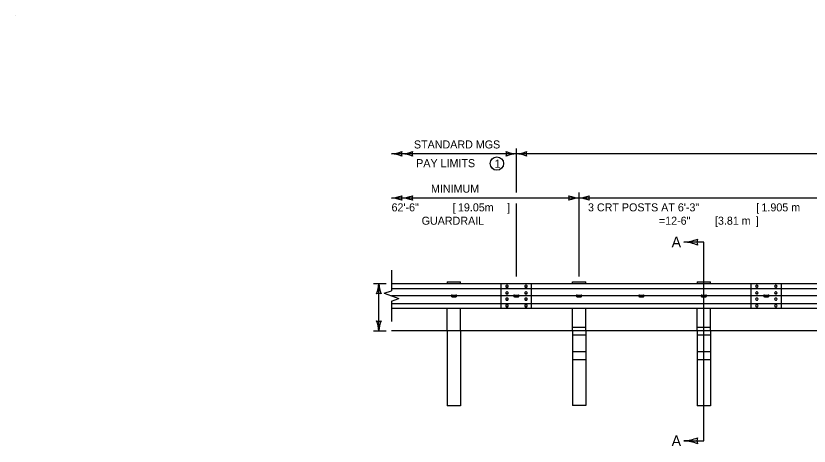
# Model space of a CAD drawing. Extents: x 49991.4 to 50044.5, y 49987.6 to 50011.4.
# Drawn here: x 50021.04 to 50026.98, y 50005.3 to 50008.52 of the extents above; entities that cross this region are included whole.
import ezdxf

# ---------------------------------------------------------------- set-up
doc = ezdxf.new("R2010")
doc.units = 0
for name, color, linetype in [('Level 1', 7, 'Continuous'), ('Level 2', 7, 'Continuous'), ('Level 3', 7, 'Continuous'), ('Level 4', 7, 'Continuous'), ('Level 5', 7, 'Continuous'), ('Level 6', 7, 'Continuous')]:
    doc.layers.add(name, color=color, linetype=linetype)

msp = doc.modelspace()

# ---------------------------------------------------------------- linework, layer by layer
at = {"layer": 'Level 1'}
for p, q in [((50021.0378, 50008.5236), (50021.0378, 50008.5236)), ((50024.2697, 50006.5335), (50024.2697, 50006.5203)), ((50024.2697, 50006.5335), (50024.3697, 50006.5335)), ((50024.3697, 50006.5203), (50024.3697, 50006.5335)), ((50025.2078, 50006.5203), (50025.2078, 50006.5335)), ((50025.2078, 50006.5335), (50025.3077, 50006.5335)), ((50025.3077, 50006.5203), (50025.3077, 50006.5335)), ((50026.1422, 50006.5335), (50026.1422, 50006.5203)), ((50026.1422, 50006.5335), (50026.2422, 50006.5335)), ((50026.2422, 50006.5203), (50026.2422, 50006.5335)), ((50023.8525, 50006.5203), (50035.1185, 50006.5203)), ((50023.8525, 50006.4843), (50035.1185, 50006.4843)), ((50024.6747, 50006.335), (50024.6747, 50006.5196)), ((50024.7189, 50006.508), (50024.7153, 50006.508)), ((50024.7189, 50006.4929), (50024.7153, 50006.4929)), ((50024.8612, 50006.508), (50024.8576, 50006.508)), ((50024.8612, 50006.4929), (50024.8576, 50006.4929)), ((50026.5472, 50006.335), (50026.5472, 50006.5196)), ((50026.5914, 50006.508), (50026.5878, 50006.508)), ((50026.5914, 50006.4929), (50026.5878, 50006.4929)), ((50026.7336, 50006.508), (50026.73, 50006.508)), ((50026.7336, 50006.4929), (50026.73, 50006.4929)), ((50024.3062, 50006.4342), (50024.3353, 50006.4342)), ((50024.3062, 50006.4217), (50024.3353, 50006.4217)), ((50024.7189, 50006.4581), (50024.7153, 50006.4581)), ((50024.7189, 50006.443), (50024.7153, 50006.443)), ((50024.7189, 50006.4116), (50024.7153, 50006.4116)), ((50024.7734, 50006.4342), (50024.8026, 50006.4342)), ((50024.7734, 50006.4217), (50024.8026, 50006.4217)), ((50024.8612, 50006.4581), (50024.8576, 50006.4581)), ((50024.8612, 50006.443), (50024.8576, 50006.443)), ((50024.8612, 50006.4116), (50024.8576, 50006.4116)), ((50025.2432, 50006.4342), (50025.2723, 50006.4342)), ((50025.2432, 50006.4217), (50025.2723, 50006.4217)), ((50025.7104, 50006.4342), (50025.7396, 50006.4342)), ((50025.7104, 50006.4217), (50025.7396, 50006.4217)), ((50026.1776, 50006.4342), (50026.2068, 50006.4342)), ((50026.1776, 50006.4217), (50026.2068, 50006.4217)), ((50026.5914, 50006.4581), (50026.5878, 50006.4581)), ((50026.5914, 50006.443), (50026.5878, 50006.443)), ((50026.5914, 50006.4116), (50026.5878, 50006.4116)), ((50026.6459, 50006.4342), (50026.675, 50006.4342)), ((50026.6459, 50006.4217), (50026.675, 50006.4217)), ((50026.7336, 50006.4581), (50026.73, 50006.4581)), ((50026.7336, 50006.443), (50026.73, 50006.443)), ((50026.7336, 50006.4116), (50026.73, 50006.4116)), ((50023.8525, 50006.3717), (50035.1185, 50006.3717)), ((50024.7189, 50006.3965), (50024.7153, 50006.3965)), ((50024.7189, 50006.3617), (50024.7153, 50006.3617)), ((50024.7189, 50006.3466), (50024.7153, 50006.3466)), ((50024.8612, 50006.3965), (50024.8576, 50006.3965)), ((50024.8612, 50006.3617), (50024.8576, 50006.3617)), ((50024.8612, 50006.3466), (50024.8576, 50006.3466)), ((50026.5914, 50006.3965), (50026.5878, 50006.3965)), ((50026.5914, 50006.3617), (50026.5878, 50006.3617)), ((50026.5914, 50006.3466), (50026.5878, 50006.3466)), ((50026.7336, 50006.3965), (50026.73, 50006.3965)), ((50026.7336, 50006.3617), (50026.73, 50006.3617)), ((50026.7336, 50006.3466), (50026.73, 50006.3466)), ((50023.8525, 50006.3357), (50035.1185, 50006.3357)), ((50024.2697, 50006.1659), (50024.2697, 50006.3357)), ((50024.3697, 50006.1659), (50024.3697, 50006.3357)), ((50025.2077, 50006.1659), (50025.2077, 50006.3357)), ((50025.3077, 50006.1659), (50025.3077, 50006.3357)), ((50026.1422, 50006.1659), (50026.1422, 50006.3357)), ((50026.2421, 50006.1659), (50026.2421, 50006.3357)), ((50035.1185, 50006.1659), (50023.8525, 50006.1659))]:
    msp.add_line(p, q, dxfattribs=at)
for centre, start, end in [((50024.3062, 50006.428), 90, 180), ((50024.3062, 50006.428), 180, 270), ((50024.3353, 50006.428), 360, 90), ((50024.3353, 50006.428), 270, 0), ((50024.7734, 50006.428), 90, 180), ((50024.7734, 50006.428), 180, 270), ((50024.8026, 50006.428), 360, 90), ((50024.8026, 50006.428), 270, 0), ((50025.2432, 50006.428), 90, 180), ((50025.2432, 50006.428), 180, 270), ((50025.2723, 50006.428), 360, 90), ((50025.2723, 50006.428), 270, 0), ((50025.7104, 50006.428), 90, 180), ((50025.7104, 50006.428), 180, 270), ((50025.7396, 50006.428), 360, 90), ((50025.7396, 50006.428), 270, 0), ((50026.1776, 50006.428), 90, 180), ((50026.1776, 50006.428), 180, 270), ((50026.2068, 50006.428), 360, 90), ((50026.2068, 50006.428), 270, 0), ((50026.6459, 50006.428), 90, 180), ((50026.6459, 50006.428), 180, 270), ((50026.675, 50006.428), 360, 90), ((50026.675, 50006.428), 270, 0)]:
    msp.add_arc(centre, 0.00625, start, end, dxfattribs=at)
for centre, start_param, end_param in [((50024.7153, 50006.5004), 1.570796, 4.712389), ((50024.7189, 50006.5004), 4.712389, 7.853982), ((50024.8576, 50006.5004), 1.570796, 4.712389), ((50024.8612, 50006.5004), 4.712389, 7.853982), ((50026.5878, 50006.5004), 1.570796, 4.712389), ((50026.5914, 50006.5004), 4.712389, 7.853982), ((50026.73, 50006.5004), 1.570796, 4.712389), ((50026.7336, 50006.5004), 4.712389, 7.853982), ((50024.7153, 50006.4505), 1.570796, 4.712389), ((50024.7153, 50006.404), 1.570796, 4.712389), ((50024.7189, 50006.4505), 4.712389, 7.853982), ((50024.7189, 50006.404), 4.712389, 7.853982), ((50024.8576, 50006.4505), 1.570796, 4.712389), ((50024.8576, 50006.404), 1.570796, 4.712389), ((50024.8612, 50006.4505), 4.712389, 7.853982), ((50024.8612, 50006.404), 4.712389, 7.853982), ((50026.5878, 50006.4505), 1.570796, 4.712389), ((50026.5878, 50006.404), 1.570796, 4.712389), ((50026.5914, 50006.4505), 4.712389, 7.853982), ((50026.5914, 50006.404), 4.712389, 7.853982), ((50026.73, 50006.4505), 1.570796, 4.712389), ((50026.73, 50006.404), 1.570796, 4.712389), ((50026.7336, 50006.4505), 4.712389, 7.853982), ((50026.7336, 50006.404), 4.712389, 7.853982), ((50024.7153, 50006.3541), 1.570796, 4.712389), ((50024.7189, 50006.3541), 4.712389, 7.853982), ((50024.8576, 50006.3541), 1.570796, 4.712389), ((50024.8612, 50006.3541), 4.712389, 7.853982), ((50026.5878, 50006.3541), 1.570796, 4.712389), ((50026.5914, 50006.3541), 4.712389, 7.853982), ((50026.73, 50006.3541), 1.570796, 4.712389), ((50026.7336, 50006.3541), 4.712389, 7.853982)]:
    msp.add_ellipse(centre, major_axis=(0.00756, 0), ratio=0.998676, start_param=start_param, end_param=end_param, dxfattribs=at)
at = {"layer": 'Level 2'}
msp.add_circle((50024.6418, 50007.4187), 0.05, dxfattribs=at)
at = {"layer": 'Level 3'}
for p, q in [((50035.1185, 50007.4915), (50023.8525, 50007.4915)), ((50024.788, 50007.2007), (50024.788, 50007.5315)), ((50025.2577, 50006.5736), (50025.2577, 50007.2007)), ((50025.2577, 50007.1607), (50023.8525, 50007.1607)), ((50024.788, 50006.5734), (50024.788, 50007.1207)), ((50027.1302, 50007.1607), (50025.2577, 50007.1607)), ((50023.7176, 50006.5203), (50023.8125, 50006.5203)), ((50023.7576, 50006.1659), (50023.7576, 50006.5203)), ((50023.7176, 50006.1659), (50023.8125, 50006.1659))]:
    msp.add_line(p, q, dxfattribs=at)
for centre, radius, start, end in [((50023.841, 50007.7242), 0.233, 272.82731, 292.07716), ((50023.8433, 50007.2694), 0.2223, 67.45601, 87.63952), ((50023.9807, 50007.4915), 0.0548, 162.13882, 197.86118), ((50023.9209, 50007.7242), 0.233, 272.82731, 292.07716), ((50023.9232, 50007.2694), 0.2223, 67.45601, 87.63952), ((50024.0606, 50007.4915), 0.0548, 162.13882, 197.86118), ((50024.7971, 50007.7137), 0.2223, 247.45601, 267.63952), ((50024.6598, 50007.4915), 0.0548, 342.13882, 17.86118), ((50024.7995, 50007.2588), 0.233, 92.82731, 112.07716), ((50024.7765, 50007.7242), 0.233, 272.82731, 292.07716), ((50024.7788, 50007.2694), 0.2223, 67.45601, 87.63952), ((50024.9162, 50007.4915), 0.0548, 162.13882, 197.86118), ((50023.841, 50007.3934), 0.233, 272.82731, 292.07716), ((50023.9807, 50007.1607), 0.0548, 162.13882, 197.86118), ((50023.9209, 50007.3934), 0.233, 272.82731, 292.07716), ((50024.0606, 50007.1607), 0.0548, 162.13882, 197.86118), ((50025.2669, 50007.3829), 0.2223, 247.45601, 267.63952), ((50025.1295, 50007.1607), 0.0548, 342.13882, 17.86118), ((50025.2486, 50007.3829), 0.2223, 272.36048, 292.54399), ((50025.386, 50007.1607), 0.0548, 162.13882, 197.86118), ((50023.8433, 50006.9386), 0.2223, 67.45601, 87.63952), ((50023.9232, 50006.9386), 0.2223, 67.45601, 87.63952), ((50025.2692, 50006.928), 0.233, 92.82731, 112.07716), ((50025.2463, 50006.928), 0.233, 67.92284, 87.17269), ((50026.0308, 50007.1273), 0.2964, 272.36048, 292.54399), ((50026.0277, 50006.5208), 0.3107, 67.92284, 87.17269), ((50026.214, 50006.8311), 0.073, 162.13882, 197.86118), ((50023.5355, 50006.5294), 0.2223, 337.45601, 357.63952), ((50023.9903, 50006.5318), 0.233, 182.82731, 202.07716), ((50023.7576, 50006.3921), 0.0548, 72.13882, 107.86118), ((50023.7576, 50006.2941), 0.0548, 252.13882, 287.86118), ((50023.5249, 50006.1544), 0.233, 2.82731, 22.07716), ((50023.9797, 50006.1568), 0.2223, 157.45601, 177.63952), ((50026.0278, 50005.6543), 0.3107, 272.82731, 292.07716), ((50026.0309, 50005.0478), 0.2964, 67.45601, 87.63952), ((50026.2141, 50005.344), 0.073, 162.13882, 197.86118)]:
    msp.add_arc(centre, radius, start, end, dxfattribs=at)
at = {"layer": 'Level 4'}
for p, q in [((50024.9012, 50006.335), (50024.9012, 50006.5196)), ((50026.7737, 50006.335), (50026.7737, 50006.5196)), ((50024.2697, 50006.1659), (50024.2697, 50005.6067)), ((50024.3697, 50006.1659), (50024.3697, 50005.6067)), ((50025.2077, 50006.1659), (50025.2077, 50005.6078)), ((50025.2078, 50006.1945), (50025.3077, 50006.1945)), ((50025.3077, 50006.1659), (50025.3077, 50005.6078)), ((50026.1422, 50006.1945), (50026.2421, 50006.1945)), ((50026.1422, 50006.1659), (50026.1422, 50005.6067)), ((50026.2421, 50006.1659), (50026.2421, 50005.6067)), ((50025.2078, 50006.1362), (50025.3077, 50006.1362)), ((50026.1422, 50006.1362), (50026.2421, 50006.1362)), ((50025.2078, 50006.0116), (50025.3077, 50006.0116)), ((50026.1422, 50006.0116), (50026.2421, 50006.0116)), ((50025.2078, 50005.9533), (50025.3077, 50005.9533)), ((50026.1422, 50005.9533), (50026.2421, 50005.9533)), ((50024.3697, 50005.6067), (50024.2697, 50005.6067)), ((50025.3077, 50005.6078), (50025.2077, 50005.6078)), ((50026.2421, 50005.6067), (50026.1422, 50005.6067))]:
    msp.add_line(p, q, dxfattribs=at)
at = {"layer": 'Level 5'}
msp.add_line((50035.1185, 50006.428), (50023.8525, 50006.428), dxfattribs=at)
at = {"layer": 'Level 6'}
for p, q in [((50026.1921, 50006.8311), (50026.0431, 50006.8311)), ((50026.1922, 50005.344), (50026.1921, 50006.8311)), ((50023.8525, 50006.6203), (50023.8525, 50006.4669)), ((50023.7976, 50006.4475), (50023.8525, 50006.4669)), ((50023.7976, 50006.4475), (50023.8525, 50006.428)), ((50023.8525, 50006.428), (50023.9073, 50006.4086)), ((50023.8525, 50006.3891), (50023.9073, 50006.4086)), ((50023.8525, 50006.3891), (50023.8525, 50006.2357)), ((50026.0432, 50005.344), (50026.1922, 50005.344))]:
    msp.add_line(p, q, dxfattribs=at)

# ---------------------------------------------------------------- texts
at = {"layer": 'Level 2'}
for s, height, p in [('STANDARD MGS', 0.06, (50024.0202, 50007.5315)), ('PAY LIMITS', 0.06, (50024.0371, 50007.3915)), ('1', 0.06, (50024.6243, 50007.3873)), ('MINIMUM', 0.06, (50024.148, 50007.2007)), (' 62\'-6" ', 0.06, (50023.8303, 50007.0607)), ('[', 0.06, (50024.3103, 50007.0607)), ('19.05m', 0.06, (50024.35, 50007.0607)), (']', 0.06, (50024.719, 50007.0607)), ('3 CRT POSTS AT 6\'-3" ', 0.06, (50025.3245, 50007.0607)), ('[', 0.06, (50026.5845, 50007.0607)), ('1.905 m', 0.06, (50026.6242, 50007.0607)), ('GUARDRAIL', 0.06, (50024.0782, 50006.9607)), ('=12-6" ', 0.06, (50025.8558, 50006.9607)), ('[3.81', 0.06, (50026.2758, 50006.9607)), (' m', 0.06, (50026.453, 50006.9607)), (']', 0.06, (50026.5819, 50006.9607)), ('A', 0.0799, (50025.9508, 50006.7911)), ('A', 0.0799, (50025.9509, 50005.304))]:
    msp.add_text(s, height=height, dxfattribs=at).set_placement(p)

doc.saveas('drawing.dxf')
